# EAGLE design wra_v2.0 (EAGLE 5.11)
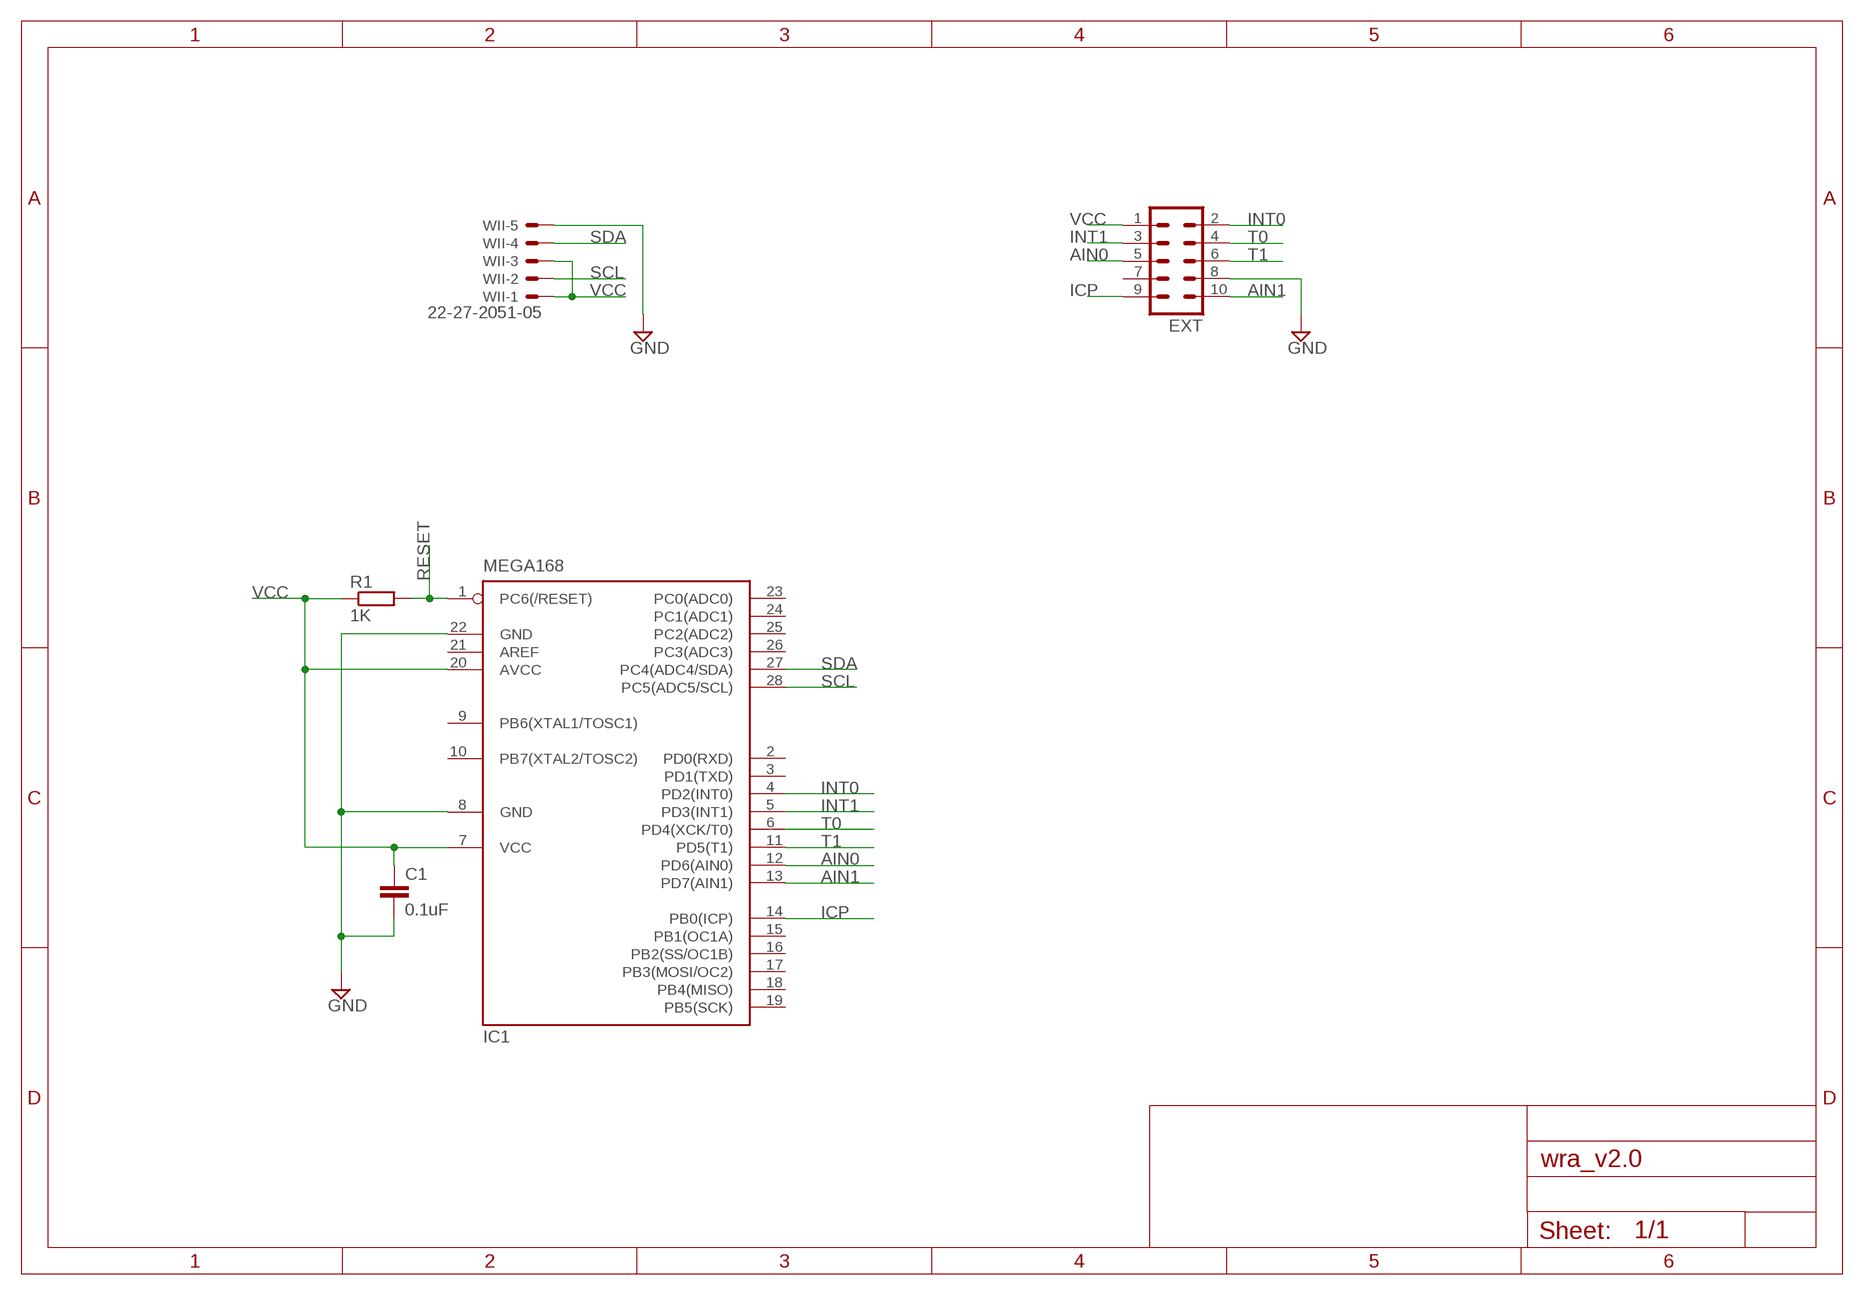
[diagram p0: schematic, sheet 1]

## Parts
C1  0.1uF  C-EU050-024X044  [C050-024X044]
EXT  ML10  [ML10]
IC1  MEGA168  MEGA8-P  [DIL28-3]
R1  1K  R-EU_0207/2V  [0207/2V]
WII  22-27-2051-05  [6410-05]

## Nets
AIN0: EXT.5 IC1.12(PD6(AIN0))
AIN1: EXT.10 IC1.13(PD7(AIN1))
GND: C1.2 EXT.8 IC1.8(GND) IC1.22(GND) WII.5
ICP: EXT.9 IC1.14(PB0(ICP))
INT0: EXT.2 IC1.4(PD2(INT0))
INT1: EXT.3 IC1.5(PD3(INT1))
RESET: IC1.1(PC6(/RESET)) R1.2
SCL: IC1.28(PC5(ADC5/SCL)) WII.2
SDA: IC1.27(PC4(ADC4/SDA)) WII.4
T0: EXT.4 IC1.6(PD4(XCK/T0))
T1: EXT.6 IC1.11(PD5(T1))
VCC: C1.1 EXT.1 IC1.7(VCC) IC1.20(AVCC) R1.1 WII.1 WII.3
Unconnected: EXT.7 IC1.2(PD0(RXD)) IC1.3(PD1(TXD)) IC1.9(PB6(XTAL1/TOSC1)) IC1.10(PB7(XTAL2/TOSC2)) IC1.15(PB1(OC1A)) IC1.16(PB2(SS/OC1B)) IC1.17(PB3(MOSI/OC2)) IC1.18(PB4(MISO)) IC1.19(PB5(SCK)) IC1.21(AREF) IC1.23(PC0(ADC0)) IC1.24(PC1(ADC1)) IC1.25(PC2(ADC2)) IC1.26(PC3(ADC3))

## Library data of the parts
C1 = rcl:C-EU: CAPACITOR, European symbol
EXT = con-ml:ML10: HARTING; OC_FARNELL: unknown; OC_NEWARK: unknown
IC1 = atmel:MEGA8-P: MICROCONTROLLER 8 Kbytes FLASH, 1 kbytes SRAM, 512 bytes EEPROM, USART, 4-channel 10 bit ADC, 2-channel 8 bit ADC Pin compatible with Atmega48, ATMega88, ATMega168 Source: avr.lbr; OC_FARNELL: unknown; OC_NEWARK: unknown
R1 = rcl:R-EU_: RESISTOR, European symbol
WII = con-molex:22-?-05: CONNECTOR wire to board 2.54 mm (.1 inch) pitch header; OC_FARNELL: unknown; OC_NEWARK: unknown

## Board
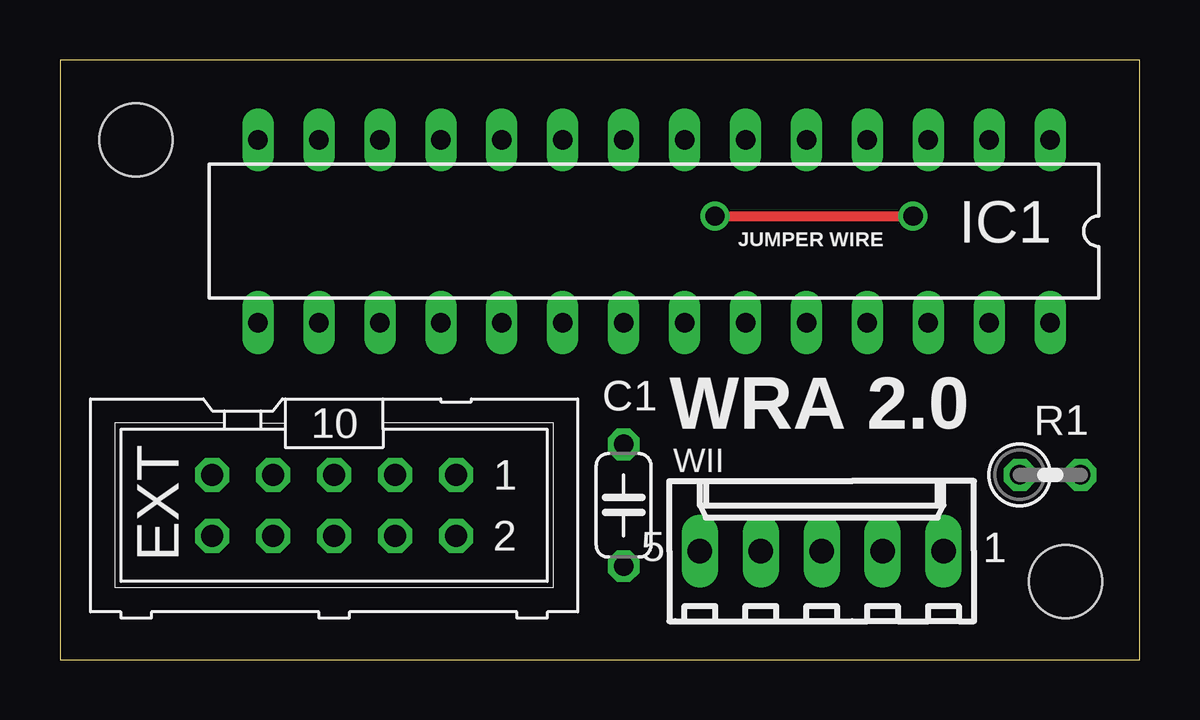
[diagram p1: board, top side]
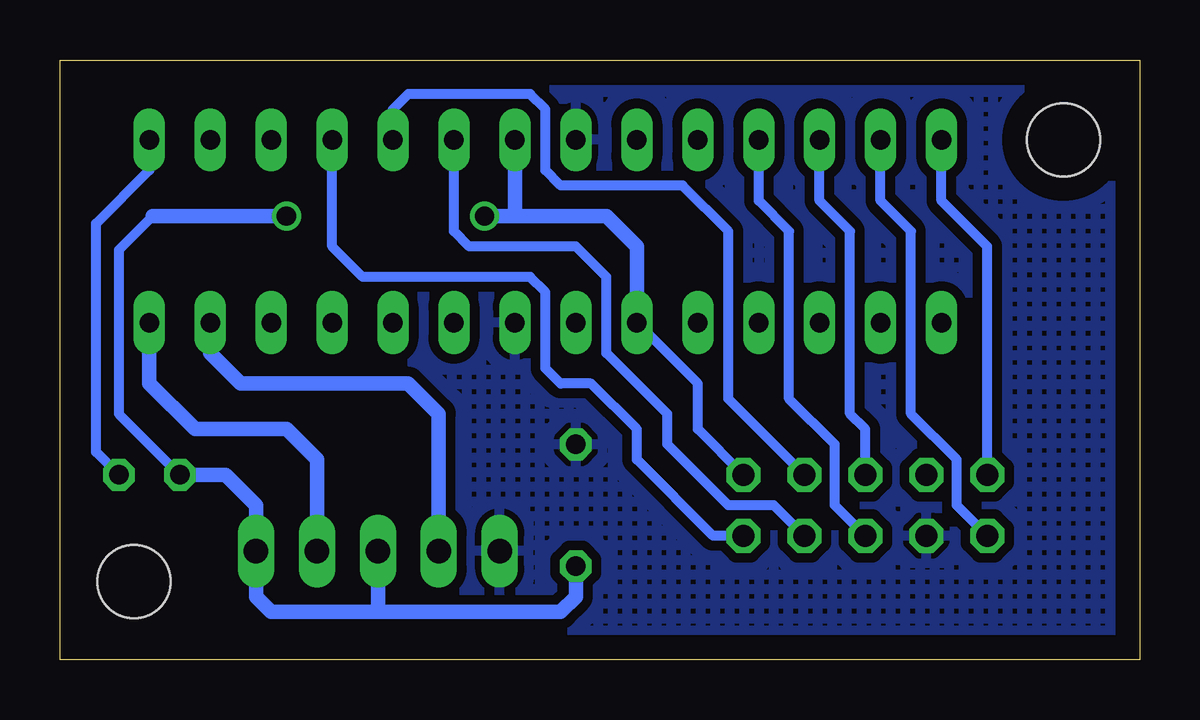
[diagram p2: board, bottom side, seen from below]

Size 45 x 25 mm. Coordinates in mm from the lower left corner, seen from the top.
Outline: 0,0 45,0 45,25 0,25 0,0
Copper layers (1*16): Top 0.035mm / dielectric 1.5mm / Bottom 0.035mm
Design rules "default *": minimum track width 8mil, minimum drill 24mil, track to track 8mil, track to pad 8mil, pad to pad 8mil, via to via 8mil, smd to smd 8mil, copper to edge 40mil, drill to drill 8mil, minimum pad ring 10mil, minimum via ring 8mil, stop-mask expansion 4mil, vias tented up to drill 0mil, thermal gap 10mil

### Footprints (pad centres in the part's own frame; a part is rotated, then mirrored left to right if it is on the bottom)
C050-024X044 = drill 0.813 octagon: 1 -2.54,0; 2 2.54,0
ML10 = drill 0.914 octagon: 1 -5.08,-1.27; 2 -5.08,1.27; 3 -2.54,-1.27; 4 -2.54,1.27; 5 0,-1.27; 6 0,1.27; 7 2.54,-1.27; 8 2.54,1.27; 9 5.08,-1.27; 10 5.08,1.27
DIL28-3 = drill 0.813 long: 1 -16.51,-3.81; 2 -13.97,-3.81; 3 -11.43,-3.81; 4 -8.89,-3.81; 5 -6.35,-3.81; 6 -3.81,-3.81; 7 -1.27,-3.81; 8 1.27,-3.81; 9 3.81,-3.81; 10 6.35,-3.81; 11 8.89,-3.81; 12 11.43,-3.81; 13 13.97,-3.81; 14 16.51,-3.81; 15 16.51,3.81; 16 13.97,3.81; 17 11.43,3.81; 18 8.89,3.81; 19 6.35,3.81; 20 3.81,3.81; 21 1.27,3.81; 22 -1.27,3.81; 23 -3.81,3.81; 24 -6.35,3.81; 25 -8.89,3.81; 26 -11.43,3.81; 27 -13.97,3.81; 28 -16.51,3.81
0207/2V = drill 0.813 octagon: 1 -1.27,0; 2 1.27,0
STAND-OFF-TIGHT = hole 3.048: 0,0
6410-05 = drill 1.016 long: 1 5.08,0; 2 2.54,0; 3 0,0; 4 -2.54,0; 5 -5.08,0

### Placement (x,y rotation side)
C1  23.5,6.43 90 top
EXT  11.43,6.43 180 top
IC1  24.77,17.86 180 top
R1  41.27,7.7 0 top
U$2  [STAND-OFF-TIGHT]  41.91,3.26 0 top
U$3  [STAND-OFF-TIGHT]  3.17,21.67 0 top
WII  31.75,4.53 0 top

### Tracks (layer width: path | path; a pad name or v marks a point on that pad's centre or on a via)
AIN0
  Bottom 0.406: IC1.12 13.34,19.13 12.06,17.86 12.06,10.24 11.43,9.61 EXT.5
AIN1
  Bottom 0.406: EXT.10 7.62,6.43 7.62,8.34 9.53,10.24 9.53,17.86 10.79,19.13 IC1.13
GND
  pour Bottom (isolate 0.406, hatched): 0,25 45,25 45,0 0,0
ICP
  Bottom 0.406: EXT.9 6.35,17.23 8.26,19.13 IC1.14
INT0
  Bottom 0.406: IC1.4 33.66,17.23 32.38,15.95 25.4,15.95 24.77,15.32 24.77,12.14 24.13,11.51 22.86,11.51 20.95,9.61 20.95,8.34 17.78,5.16 EXT.2
INT1
  Bottom 0.406: EXT.3 17.14,10.88 17.14,17.86 19.05,19.77 24.13,19.77 24.77,20.4 24.77,22.94 25.4,23.57 30.48,23.57 31.11,22.94 IC1.5
RESET
  Bottom 0.406: IC1.1 41.27,20.4 43.5,18.18 43.5,8.65 R1.2
SCL
  Bottom 0.61: IC1.28 41.27,11.51 39.37,9.61 35.56,9.61 34.29,8.34 WII.2
SDA
  Bottom 0.61: IC1.27 38.73,12.78 37.47,11.51 30.48,11.51 29.21,10.24 WII.4
T0
  Bottom 0.406: IC1.6 28.57,17.86 27.94,17.23 23.5,17.23 22.23,15.95 22.23,12.78 19.68,10.24 19.68,8.97 17.14,6.43 15.24,6.43 EXT.4
T1
  Bottom 0.406: EXT.6 12.7,6.43 12.7,8.97 14.61,10.88 14.61,17.86 15.88,19.13 IC1.11
VCC  (via drill 0.8)
  Top 0.406: v27.3,18.5 v35.56,18.5
  Bottom 0.406: 41.12,18.5 42.55,17.07 42.55,10.24 R1.1 | IC1.20 18.41,11.51 18.41,9.61 EXT.1
  Bottom 0.61: v35.56,18.5 41.12,18.5 | R1.1 38.1,7.7 36.83,6.43 WII.1 36.83,2.62 36.2,1.99 31.75,1.99 | 31.75,1.99 24.13,1.99 23.5,2.62 C1.1 | 31.75,1.99 WII.3 | 26.04,18.5 v27.3,18.5 | 26.04,18.5 IC1.7 | 26.04,18.5 22.23,18.5 20.95,17.23 IC1.20

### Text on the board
tPlace: WRA 2.0
tNames: JUMPER WIRE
